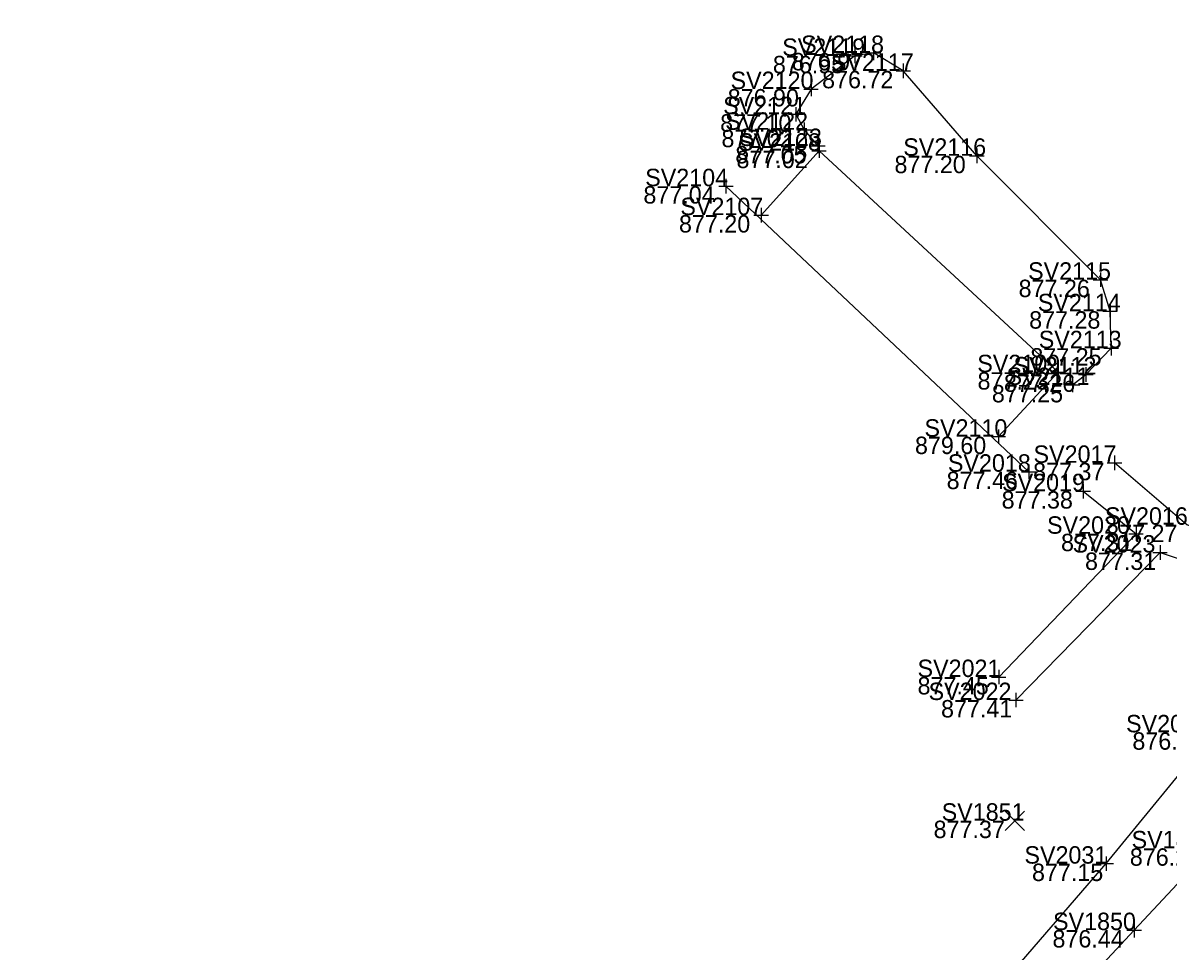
# Model space of a CAD drawing. Extents: x 1480001 to 1480402, y 379235 to 379603.
# Drawn here: x 1480035.5 to 1480114.4, y 379370.1 to 379434.1 of the extents above; entities that cross this region are included whole.
import ezdxf

# ---------------------------------------------------------------- set-up
doc = ezdxf.new("R2010")
doc.units = 0
for name, color, linetype in [('BD_X_Building', 7, 'Continuous'), ('BD_X_Porch_or_Deck', 7, 'Continuous'), ('PV_X_Walk', 7, 'Continuous'), ('SV_X_Break_Lines', 7, 'Continuous'), ('SV_X_Random_Point', 7, 'Continuous'), ('SV_X_Shot_Marker', 7, 'Continuous'), ('SV_X_Text_Elevation', 7, 'Continuous'), ('SV_X_Text_Name', 7, 'Continuous'), ('VG_X_Flower_Bed', 7, 'Continuous')]:
    doc.layers.add(name, color=color, linetype=linetype)

msp = doc.modelspace()

# ---------------------------------------------------------------- linework, layer by layer
at = {"layer": 'BD_X_Building'}
msp.add_line((1480104.802, 379403.171), (1480083.928, 379422.85), dxfattribs=at)
at = {"layer": 'BD_X_Porch_or_Deck'}
msp.add_lwpolyline([(1480086.359, 379420.856), (1480090.342, 379425.296), (1480106.828, 379410.03), (1480102.697, 379405.586)], dxfattribs=at)
at = {"layer": 'PV_X_Walk'}
for points in [[(1480035.484, 379289.224), (1480050.568, 379305.437), (1480062.335, 379317.896), (1480064.038, 379319.719), (1480070.805, 379327.066), (1480078.054, 379334.946), (1480079.953, 379336.866), (1480094.208, 379352.393), (1480112.048, 379371.575), (1480117.348, 379377.211), (1480119.911, 379379.906), (1480121.511, 379381.77), (1480134.604, 379395.58), (1480136.695, 379398.148), (1480138.778, 379401.149), (1480140.004, 379404.725), (1480140.577, 379408.06), (1480140.982, 379411.311), (1480140.871, 379414.584), (1480140.225, 379417.636), (1480139.184, 379419.586), (1480133.124, 379425.845), (1480132.903, 379425.968), (1480114.834, 379442.96)], [(1480132.927, 379394.064), (1480131.678, 379394.217), (1480129.623, 379395.124), (1480129.685, 379395.088), (1480115.69, 379399.516), (1480110.694, 379403.782)], [(1480108.536, 379401.827), (1480112.184, 379398.894), (1480102.722, 379389.018)], [(1480103.907, 379387.432), (1480113.836, 379397.599), (1480128.867, 379392.608), (1480129.145, 379392.467), (1480129.878, 379392.11), (1480130.393, 379392.142), (1480130.835, 379391.865)]]:
    msp.add_lwpolyline(points, dxfattribs=at)
at = {"layer": 'SV_X_Break_Lines'}
msp.add_lwpolyline([(1480102.555, 379367.391), (1480110.126, 379376.156), (1480117.553, 379385.207), (1480124.442, 379393.548)], dxfattribs=at)
at = {"layer": 'SV_X_Random_Point'}
for p, q in [((1480103.17, 379378.448), (1480104.504, 379379.783)), ((1480103.17, 379379.783), (1480104.504, 379378.448))]:
    msp.add_line(p, q, dxfattribs=at)
at = {"layer": 'SV_X_Shot_Marker'}
for p, q in [((1480094.103, 379432.532), (1480094.103, 379431.532)), ((1480092.303, 379431.833), (1480093.303, 379431.833)), ((1480092.803, 379432.333), (1480092.803, 379431.333)), ((1480092.803, 379431.833), (1480092.803, 379431.833)), ((1480093.603, 379432.032), (1480094.603, 379432.032)), ((1480094.103, 379432.032), (1480094.103, 379432.032)), ((1480096.145, 379431.297), (1480096.145, 379430.297)), ((1480095.645, 379430.797), (1480096.645, 379430.797)), ((1480096.145, 379430.797), (1480096.145, 379430.797)), ((1480089.292, 379429.547), (1480090.292, 379429.547)), ((1480089.792, 379430.047), (1480089.792, 379429.047)), ((1480089.792, 379429.547), (1480089.792, 379429.547)), ((1480088.243, 379427.807), (1480089.243, 379427.807)), ((1480088.743, 379428.307), (1480088.743, 379427.307)), ((1480088.743, 379427.807), (1480088.743, 379427.807)), ((1480089.306, 379427.237), (1480089.306, 379426.237)), ((1480088.806, 379426.737), (1480089.806, 379426.737)), ((1480089.306, 379426.737), (1480089.306, 379426.737)), ((1480089.769, 379425.62), (1480090.769, 379425.62)), ((1480090.269, 379426.12), (1480090.269, 379425.12)), ((1480090.269, 379425.62), (1480090.269, 379425.62)), ((1480090.342, 379425.796), (1480090.342, 379424.796)), ((1480101.208, 379425.447), (1480101.208, 379424.447)), ((1480089.842, 379425.296), (1480090.842, 379425.296)), ((1480090.342, 379425.296), (1480090.342, 379425.296)), ((1480100.708, 379424.947), (1480101.708, 379424.947)), ((1480101.208, 379424.947), (1480101.208, 379424.947)), ((1480083.928, 379423.35), (1480083.928, 379422.35)), ((1480083.428, 379422.85), (1480084.428, 379422.85)), ((1480083.928, 379422.85), (1480083.928, 379422.85)), ((1480085.859, 379420.856), (1480086.859, 379420.856)), ((1480086.359, 379421.356), (1480086.359, 379420.356)), ((1480086.359, 379420.856), (1480086.359, 379420.856)), ((1480109.733, 379416.905), (1480109.733, 379415.905)), ((1480109.233, 379416.405), (1480110.233, 379416.405)), ((1480109.733, 379416.405), (1480109.733, 379416.405)), ((1480110.392, 379414.73), (1480110.392, 379413.73)), ((1480109.892, 379414.23), (1480110.892, 379414.23)), ((1480110.392, 379414.23), (1480110.392, 379414.23)), ((1480110.466, 379412.184), (1480110.466, 379411.184)), ((1480109.966, 379411.684), (1480110.966, 379411.684)), ((1480110.466, 379411.684), (1480110.466, 379411.684)), ((1480106.828, 379410.53), (1480106.828, 379409.53)), ((1480106.328, 379410.03), (1480107.328, 379410.03)), ((1480106.828, 379410.03), (1480106.828, 379410.03)), ((1480107.815, 379409.65), (1480107.815, 379408.65)), ((1480108.224, 379409.875), (1480109.224, 379409.875)), ((1480108.724, 379410.375), (1480108.724, 379409.375)), ((1480108.724, 379409.875), (1480108.724, 379409.875)), ((1480107.315, 379409.15), (1480108.315, 379409.15)), ((1480107.815, 379409.15), (1480107.815, 379409.15)), ((1480102.697, 379406.086), (1480102.697, 379405.086)), ((1480102.197, 379405.586), (1480103.197, 379405.586)), ((1480102.697, 379405.586), (1480102.697, 379405.586)), ((1480110.694, 379404.282), (1480110.694, 379403.282)), ((1480104.802, 379403.671), (1480104.802, 379402.671)), ((1480110.194, 379403.782), (1480111.194, 379403.782)), ((1480110.694, 379403.782), (1480110.694, 379403.782)), ((1480104.302, 379403.171), (1480105.302, 379403.171)), ((1480104.802, 379403.171), (1480104.802, 379403.171)), ((1480108.036, 379401.827), (1480109.036, 379401.827)), ((1480108.536, 379402.327), (1480108.536, 379401.327)), ((1480108.536, 379401.827), (1480108.536, 379401.827)), ((1480112.184, 379399.394), (1480112.184, 379398.394)), ((1480111.684, 379398.894), (1480112.684, 379398.894)), ((1480112.184, 379398.894), (1480112.184, 379398.894)), ((1480113.836, 379398.099), (1480113.836, 379397.099)), ((1480113.336, 379397.599), (1480114.336, 379397.599)), ((1480113.836, 379397.599), (1480113.836, 379397.599)), ((1480102.722, 379389.518), (1480102.722, 379388.518)), ((1480102.222, 379389.018), (1480103.222, 379389.018)), ((1480102.722, 379389.018), (1480102.722, 379389.018)), ((1480103.907, 379387.932), (1480103.907, 379386.932)), ((1480103.407, 379387.432), (1480104.407, 379387.432)), ((1480103.907, 379387.432), (1480103.907, 379387.432)), ((1480110.126, 379376.656), (1480110.126, 379375.656)), ((1480109.626, 379376.156), (1480110.626, 379376.156)), ((1480110.126, 379376.156), (1480110.126, 379376.156)), ((1480112.048, 379372.075), (1480112.048, 379371.075)), ((1480111.548, 379371.575), (1480112.548, 379371.575)), ((1480112.048, 379371.575), (1480112.048, 379371.575))]:
    msp.add_line(p, q, dxfattribs=at)
at = {"layer": 'VG_X_Flower_Bed'}
msp.add_lwpolyline([(1480107.815, 379409.15), (1480108.724, 379409.875), (1480110.466, 379411.684), (1480110.392, 379414.23), (1480109.733, 379416.405), (1480101.208, 379424.947), (1480096.145, 379430.797), (1480094.103, 379432.032), (1480092.803, 379431.833), (1480089.792, 379429.547), (1480088.743, 379427.807), (1480089.306, 379426.737), (1480090.269, 379425.62)], dxfattribs=at)

# ---------------------------------------------------------------- texts
at = {"layer": 'SV_X_Text_Elevation'}
for s, p in [('876.95', (1480087.162, 379430.633)), ('876.97', (1480088.462, 379430.832)), ('876.72', (1480090.552, 379429.597)), ('876.90', (1480084.047, 379428.347)), ('877.10', (1480083.528, 379426.607)), ('877.02', (1480083.618, 379425.537)), ('877.05', (1480084.572, 379424.42)), ('877.02', (1480084.654, 379424.096)), ('877.20', (1480095.539, 379423.747)), ('877.04', (1480078.24, 379421.65)), ('877.20', (1480080.69, 379419.656)), ('877.26', (1480104.092, 379415.205)), ('877.28', (1480104.818, 379413.03)), ('877.25', (1480104.901, 379410.484)), ('877.23', (1480101.263, 379408.83)), ('877.26', (1480103.083, 379408.675)), ('877.25', (1480102.25, 379407.95)), ('879.60', (1480096.952, 379404.386)), ('877.37', (1480105.091, 379402.582)), ('877.46', (1480099.133, 379401.971)), ('877.38', (1480102.924, 379400.627)), ('877.27', (1480110.125, 379398.316)), ('877.31', (1480107.015, 379397.694)), ('877.31', (1480108.667, 379396.399)), ('877.45', (1480097.129, 379387.818)), ('877.41', (1480098.748, 379386.232)), ('876.83', (1480111.931, 379384.007)), ('877.37', (1480098.234, 379377.916)), ('876.24', (1480111.755, 379376.011)), ('877.15', (1480105.015, 379374.956)), ('876.44', (1480106.426, 379370.375))]:
    msp.add_text(s, height=1.2, dxfattribs=at).set_placement(p)
at = {"layer": 'SV_X_Text_Name'}
for s, p in [('SV2119', (1480087.806, 379431.833)), ('SV2118', (1480089.106, 379432.032)), ('SV2117', (1480091.158, 379430.797)), ('SV2120', (1480084.247, 379429.547)), ('SV2121', (1480083.735, 379427.807)), ('SV2122', (1480083.874, 379426.737)), ('SV2108', (1480084.759, 379425.296)), ('SV2123', (1480084.828, 379425.62)), ('SV2116', (1480096.145, 379424.947)), ('SV2104', (1480078.364, 379422.85)), ('SV2107', (1480080.785, 379420.856)), ('SV2115', (1480104.746, 379416.405)), ('SV2114', (1480105.414, 379414.23)), ('SV2113', (1480105.479, 379411.684)), ('SV2109', (1480101.245, 379410.03)), ('SV2112', (1480103.746, 379409.875)), ('SV2111', (1480103.261, 379409.15)), ('SV2110', (1480097.606, 379405.586)), ('SV2017', (1480105.12, 379403.782)), ('SV2018', (1480099.219, 379403.171)), ('SV2019', (1480102.953, 379401.827)), ('SV2016', (1480110.041, 379399.516)), ('SV2020', (1480106.052, 379398.894)), ('SV2023', (1480107.808, 379397.599)), ('SV2021', (1480097.128, 379389.018)), ('SV2022', (1480097.889, 379387.432)), ('SV2032', (1480111.497, 379385.207)), ('SV1851', (1480098.792, 379379.116)), ('SV1852', (1480111.878, 379377.211)), ('SV2031', (1480104.494, 379376.156)), ('SV1850', (1480106.465, 379371.575))]:
    msp.add_text(s, height=1.2, dxfattribs=at).set_placement(p)

doc.saveas('drawing.dxf')
